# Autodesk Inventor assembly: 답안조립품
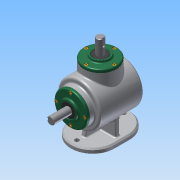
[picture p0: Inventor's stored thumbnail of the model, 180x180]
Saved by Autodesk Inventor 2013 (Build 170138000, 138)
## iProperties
Created: 2016-04
Part Number: 답안조립품
Document SubType Name: Assembly
Designer: Administrator
Author: Administrator
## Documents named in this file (14)
- C:\Users\Administrator\Desktop\460408V1006\답안조립품.iam
- C:\Users\Administrator\Desktop\460408V1006\본체.ipt
- C:\Users\Administrator\Desktop\460408V1006\커버.ipt
- C:\Users\Administrator\Desktop\460408V1006\베어링 6203.ipt
- C:\Users\Administrator\Desktop\460408V1006\오일실 17 32 8.ipt
- C:\Users\Administrator\Desktop\460408V1006\M4.ipt
- C:\Users\Administrator\Desktop\460408V1006\메인 축.ipt
- 메인 축.ipt
- C:\Users\Administrator\Desktop\460408V1006\서브 축.ipt
- 서브 축.ipt
- C:\Users\Administrator\Desktop\460408V1006\키 5x5.ipt
- C:\Users\Administrator\Desktop\460408V1006\키 4x4.ipt
- C:\Users\Administrator\Desktop\460408V1006\메인 베벨기어.ipt
- C:\Users\Administrator\Desktop\460408V1006\서브 베벨기어.ipt
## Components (8 placed, 1 different names)
1. M4:2
2. M4:3
3. M4:4
4. M4:5
5. M4:1
6. M4:6
7. M4:7
8. M4:8
